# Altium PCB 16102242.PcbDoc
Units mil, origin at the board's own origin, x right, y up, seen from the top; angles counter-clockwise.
Board outline 3150 x 1475 mil, 2 copper layers (Top Layer, Bottom Layer); 14 components, 12 nets, 39 pads, 0 vias.
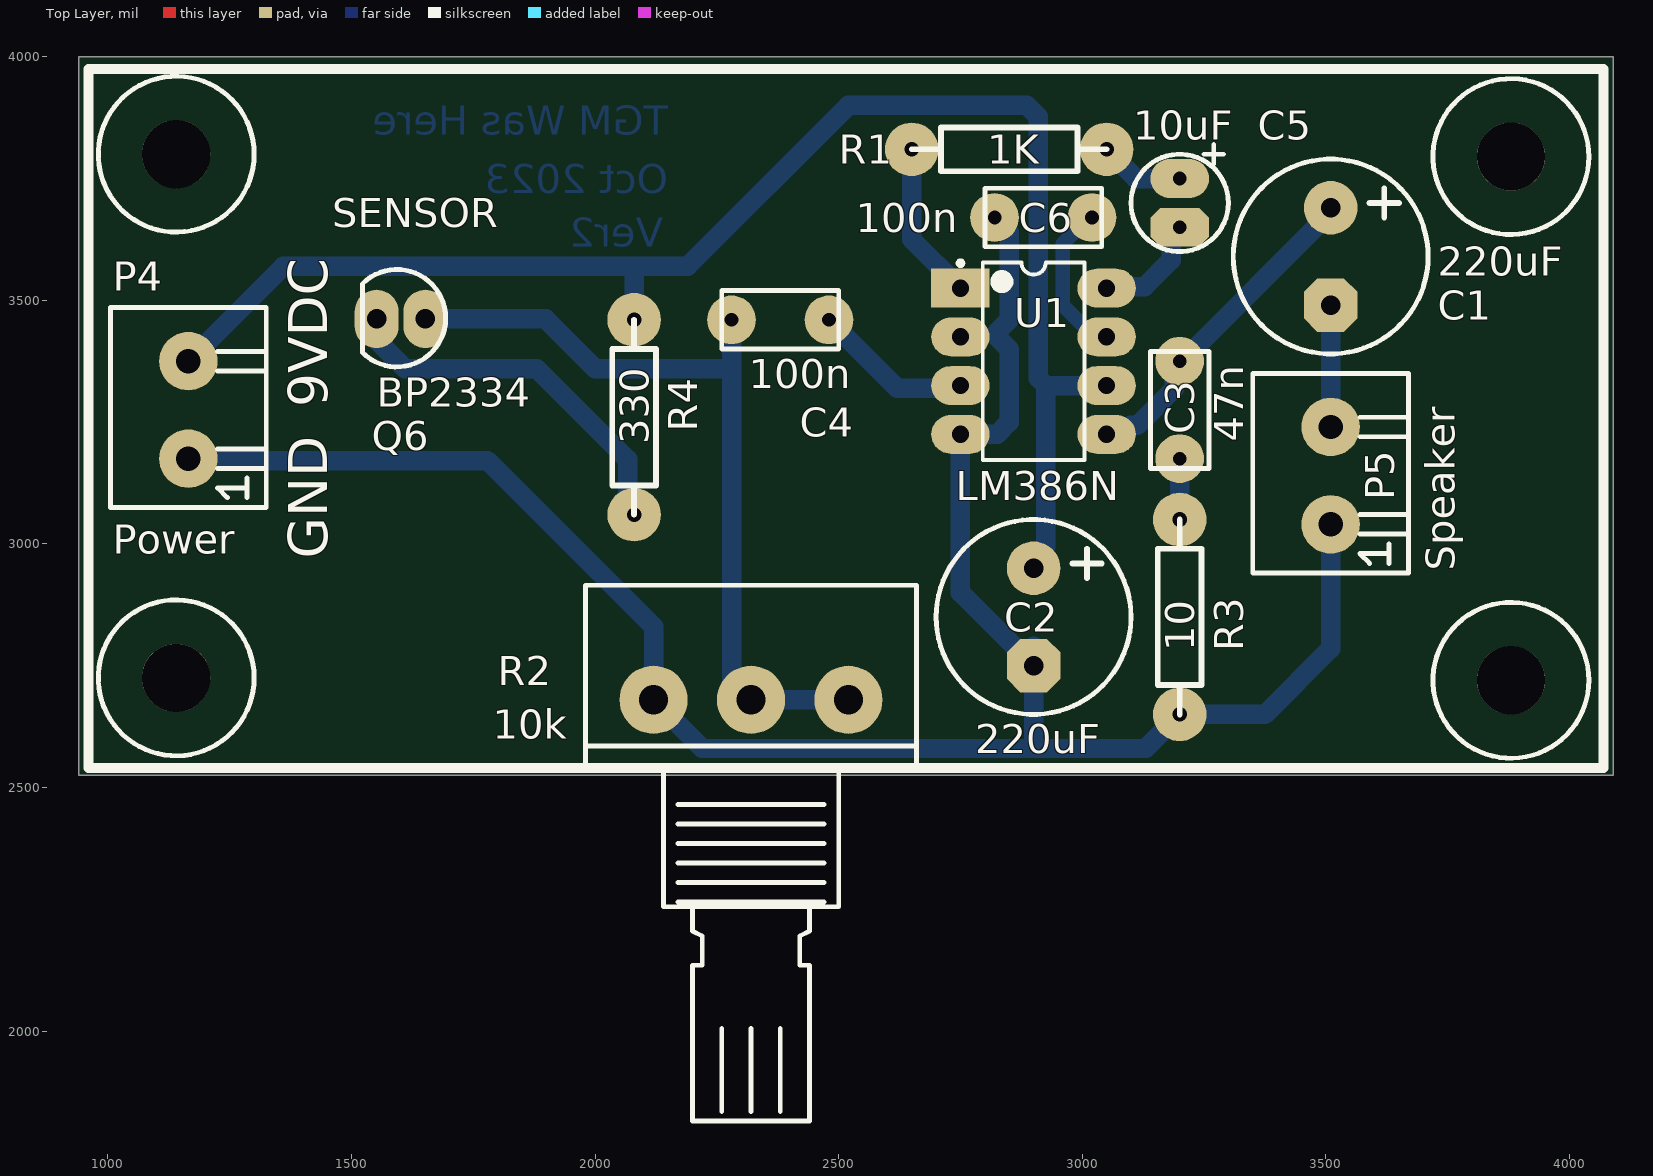
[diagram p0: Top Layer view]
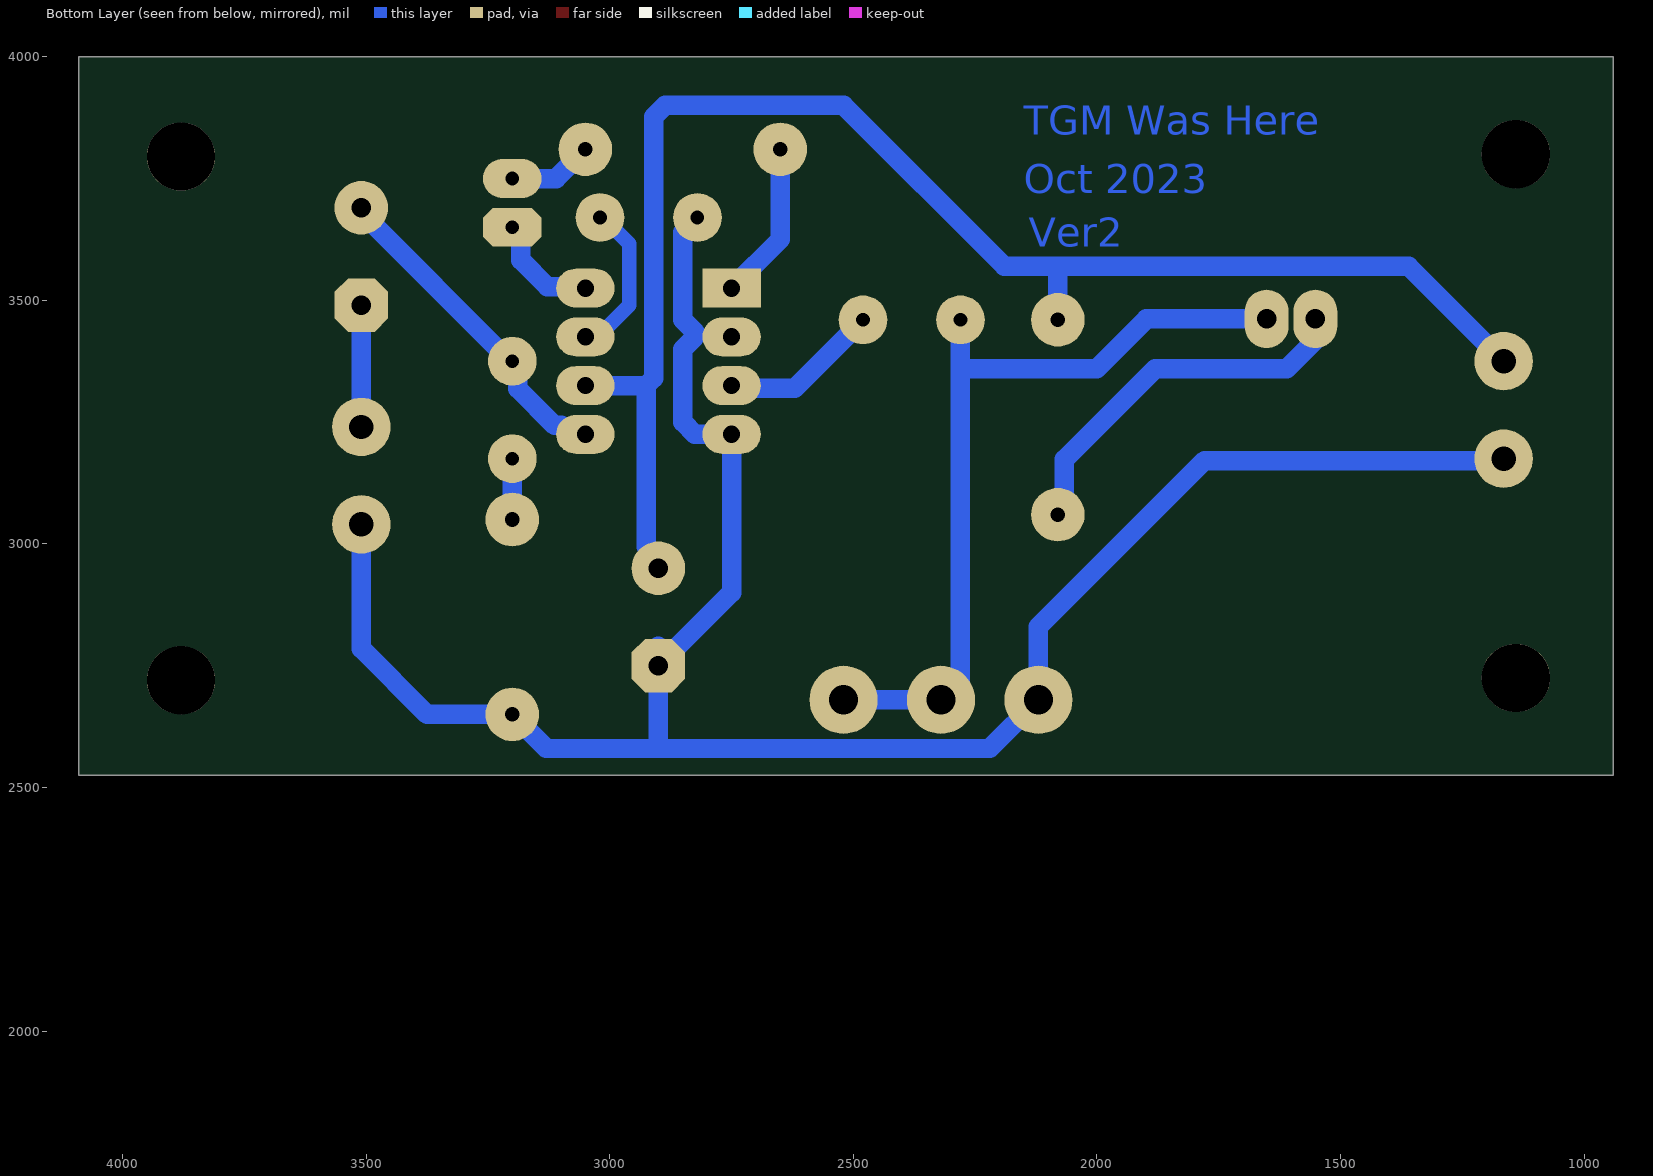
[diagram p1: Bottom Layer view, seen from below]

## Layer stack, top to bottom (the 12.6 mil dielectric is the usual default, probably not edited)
Top Solder: solder mask 0.4, Solder Resist, Dk 3.5
Top Layer: signal copper 1.4
Dielectric 1: dielectric 12.6, FR-4, Dk 4.8
Bottom Layer: signal copper 1.4
Bottom Solder: solder mask 0.4, Solder Resist, Dk 3.5

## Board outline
940,2525 4090,2525 4090,4000 940,4000

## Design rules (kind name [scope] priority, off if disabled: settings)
Clearance [All] p1: gap=10 ignorepadtopadclearanceinfootprint=FALSE except(0: Arc-Hole Track-Hole SMDPad-Hole THPad-Hole Via-Hole Fill-Hole Poly-Hole Region-Hole Text-Hole)
HoleSize [All] p1: absolutevalues=TRUE maxlimit=300 minlimit=1 maxpercent=80.000 minpercent=20.000
PolygonConnect [All] p1: connectstyle=Relief reliefconductorwidth=10 reliefentries=4 polygonreliefangle="90 Angle" airgapwidth=10
RoutingVias [All] p1: holewidth=28 width=50 viastyle="Through Hole" minholewidth=28 minwidth=50 maxholewidth=28 maxwidth=50
SolderMaskExpansion [All] p1: expansion=4 istentingtop=FALSE
Width [All] p1: maxlimit=250 minlimit=10 preferedwidth=40
29 further rules are at their usual default settings.

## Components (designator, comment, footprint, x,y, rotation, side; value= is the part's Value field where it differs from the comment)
C1 "220uF" RB.2/.4 3510,3690 r90 top value=10uF
C2 "220uF" RB.2/.4 2900,2950 r90 top value=10uF
C3 "47n" AXIAL0.2-CAP 3200,3375 r270 top
C4 "100n" AXIAL0.2-CAP 2480,3460 r180 top
C5 "10uF" RB.1/.2 3200,3650 r90 top
C6 "100n" AXIAL0.2-CAP 3020,3670 r180 top
P4 "Power" CON2_SCREW 1165,3175 r0 top (schematic designator P1)
P5 "Speaker" CON2_SCREW 3510,3040 r0 top (schematic designator P2)
Q6 "BP2334" "NPN Phototransistor" 1550,3460 r0 top (schematic designator Q1)
R1 "1K" AXIAL0.4 3050,3810 r180 top
R2 "10k" "POT-SINGLE - 16mm" 2320,2655 r0 top
R3 "10" AXIAL0.4 3200,3050 r270 top
R4 "330" AXIAL0.4 2080,3460 r270 top
U1 "LM386N" N08E 2900,3375 r0 top

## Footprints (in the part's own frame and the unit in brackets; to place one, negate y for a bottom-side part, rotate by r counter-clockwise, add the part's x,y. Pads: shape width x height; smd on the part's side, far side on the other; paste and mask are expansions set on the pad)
AXIAL0.2-CAP [mil]
  round 100 hole 28: 1(0,0) 2(200,0)
  silkscreen extent -20,-60 220,60, body extent -25,-65 225,65, height 200
AXIAL0.4 [mil] "resistor"
  round 110 hole 30: 1(0,0) 2(400,0)
  silkscreen extent 0,-45 400,45, body extent -5,-50 405,50, height 100
CON2_SCREW [mil]
  round 120 hole 50: 1(0,0) 2(0,200)
  silkscreen extent -160,-100 160,310, body extent -160,-100 160,310, height 301
N08E [mil] "DIP, 8-Leads, Row Spacing 7.62mm, Pitch 2.54mm, Body 9.91x6.35mm"
  rect 120x80 hole 35.43: 1(-150,150)
  oval 120x80 hole 35.43: 2(-150,50) 3(-150,-50) 4(-150,-150) 5(150,-150) 6(150,-50) 7(150,50) 8(150,150)
  silkscreen extent -155,-203 104,206, body extent -142,-203 142,203, height 210
"NPN Phototransistor" [mil] "Altronics p/n Z1613"
  oval 90x120 hole 40: C(1.48,1.77) E(101.48,1.77)
  silkscreen extent -28,-97 143,103
"POT-SINGLE - 16mm" [mil]
  round 140 hole 60: 1(-200,25) 2(0,25) 3(200,25)
  silkscreen extent -340,-840 340,260
RB.1/.2 [mil]
  oval 80x120 hole 28: 1(100,0)
  oct 80x120 hole 28: 2(0,0)
  silkscreen extent -50,-100 170,100, body extent -50,-100 150,100, height 400
RB.2/.4 [mil]
  round 110 hole 40: 1(0,0)
  oct 110x110 hole 40: 2(-200,0)
  silkscreen extent -300,-200 100,200, body extent -300,-200 100,200, height 1000

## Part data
C1 C2: library part "Cap Pol1", "Altronics p/n R5143"
C3: library part CAP, "Altronics p/n R3021B"
C4 C6: library part Cap, "Altronics p/n R3025B"
C5: library part "Cap Pol1", "Altronics p/n R5065"
P4 P5: library part "Header 2", "Altronics p/n P2032B"
Q6: library part Phototransistor_NPN, "Altronics p/n Z1613"
R1: library part RES2, "Altronics p/n R7558"
R2: library part POT-SINGLE, "Altronics p/n R2233"
R3: library part RES2, "Altronics p/n R7510"
R4: library part RES2, "Altronics p/n R7546"
U1: library part LM386N-1/NOPB, "Low Voltage Audio Power Amplifier, 8-pin MDIP, Pb-Free", Manufacturer="National Semiconductor", PackageTopMarking=NSUZXYTTE#*LM*386N-1, PowerWise=N, Supplier Part Number 1=LM386N-1-ND

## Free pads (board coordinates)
  round 140 hole 140: 2(1140,2725) 2(1140,3800) 2(3880,2720) 2(3880,3795)

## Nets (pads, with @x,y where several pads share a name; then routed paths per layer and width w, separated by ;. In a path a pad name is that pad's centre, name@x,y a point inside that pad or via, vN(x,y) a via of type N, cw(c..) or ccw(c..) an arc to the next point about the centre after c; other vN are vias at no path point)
+9V: C2.1 P4.2 R4.1 U1.6 | length 3150.3
  Bottom Layer w40: P4.2 1360,3570 2080,3570 ; R4.1 2080,3570 ; C2.1 2900,2968.94 2925,2993.94 2925,3325 ; U1.6 2925,3325 ; 2080,3570 2190,3570 2520,3900 2886.57,3900 2910,3876.57 2910,3340 2925,3325
GND: C2.2 C6.2 P4.1 P5.1 R2.1 R3.2 U1.2 U1.4 | length 4334
  Bottom Layer w40: P4.1 1169,3171 1779,3171 2120,2830 R2.1 2220,2580 2910,2580 ; C6.2 2850,3640 2850,3460 2825,3435 2825,3425 2850,3400 2850,3250 2825,3225 U1.4 2750,2900 C2.2 ; C2.2@2900,2790 C2.2 ; P5.1 3510,2785 3375,2650 R3.2 3130,2580 2910,2580 ; C2.2 2900,2590 2910,2580
NetC1_1: C1.1 C3.1 U1.5 | length 692.9
  Bottom Layer w40: U1.5 3080.82,3225 3099.03,3243.21 3113.21,3243.21 3188.52,3318.52 3188.52,3363.52 C3.1@3205.71,3380.71 ; C3.1 3205,3375 3510,3680 C1.1
NetC1_2: C1.2 P5.2 | length 254.1
  Bottom Layer w40: C1.2 3510,3250 P5.2@3520,3240
NetC3_2: C3.2 R3.1 | length 125
  Bottom Layer w40: R3.1 C3.2
NetC4_1: C4.1 U1.3 | length 330.1
  Bottom Layer w40: C4.1 2620,3320 2745,3320 U1.3
NetC4_2: C4.2 Q6.E R2.2 R2.3 | length 1667.2
  Bottom Layer w40: Q6.E 1898.23,3461.77 2000,3360 2280,3360 ; C4.2 2280,3360 ; R2.3 R2.2 2280,2720 2280,3360
NetC5_1: C5.1 R1.1 | length 174.9
  Bottom Layer w40: R1.1 3110,3750 C5.1
NetC5_2: C5.2 U1.8 | length 231.1
  Bottom Layer w40: U1.8 3053.21,3528.21 3128.21,3528.21 3182.57,3582.57 3182.57,3632.57 C5.2
NetC6_1: C6.1 U1.7 | length 325.1
  Bottom Layer w30: C6.1@3014.26,3670 2960,3615.74 2960,3490 U1.7@3025,3425
  Bottom Layer w40: C6.1@3014.26,3670 C6.1 ; U1.7@3025,3425 U1.7
NetQ1_C: Q6.C R4.2 | length 780.1
  Bottom Layer w40: Q6.C 1550,3460.29 1550,3420 1610,3360 1880,3360 2066.61,3173.39 2066.61,3073.39 R4.2
NetR1_2: R1.2 U1.1 | length 326.4
  Bottom Layer w40: R1.2 2650,3625 U1.1

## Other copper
Bottom Layer:
  text "TGM Was Here" at 2150,3840 h60
  text "Oct 2023" at 2150,3720 h60
  text "Ver2" at 2140,3610 h60

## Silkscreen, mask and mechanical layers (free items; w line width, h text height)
Top Overlay:
  circle w10: c1140,3800 r160
  circle w10: c1140,2725 r160
  circle w10: c3880,2720 r160
  circle w10: c3880,3795 r160
  lines w20: 960,2540 960,3975 4070,3975 4070,2540 960,2540
  text "SENSOR" at 1460,3650 h60
  text "9VDC" at 1450,3280 h80 r90
  text "GND" at 1450,2970 h80 r90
